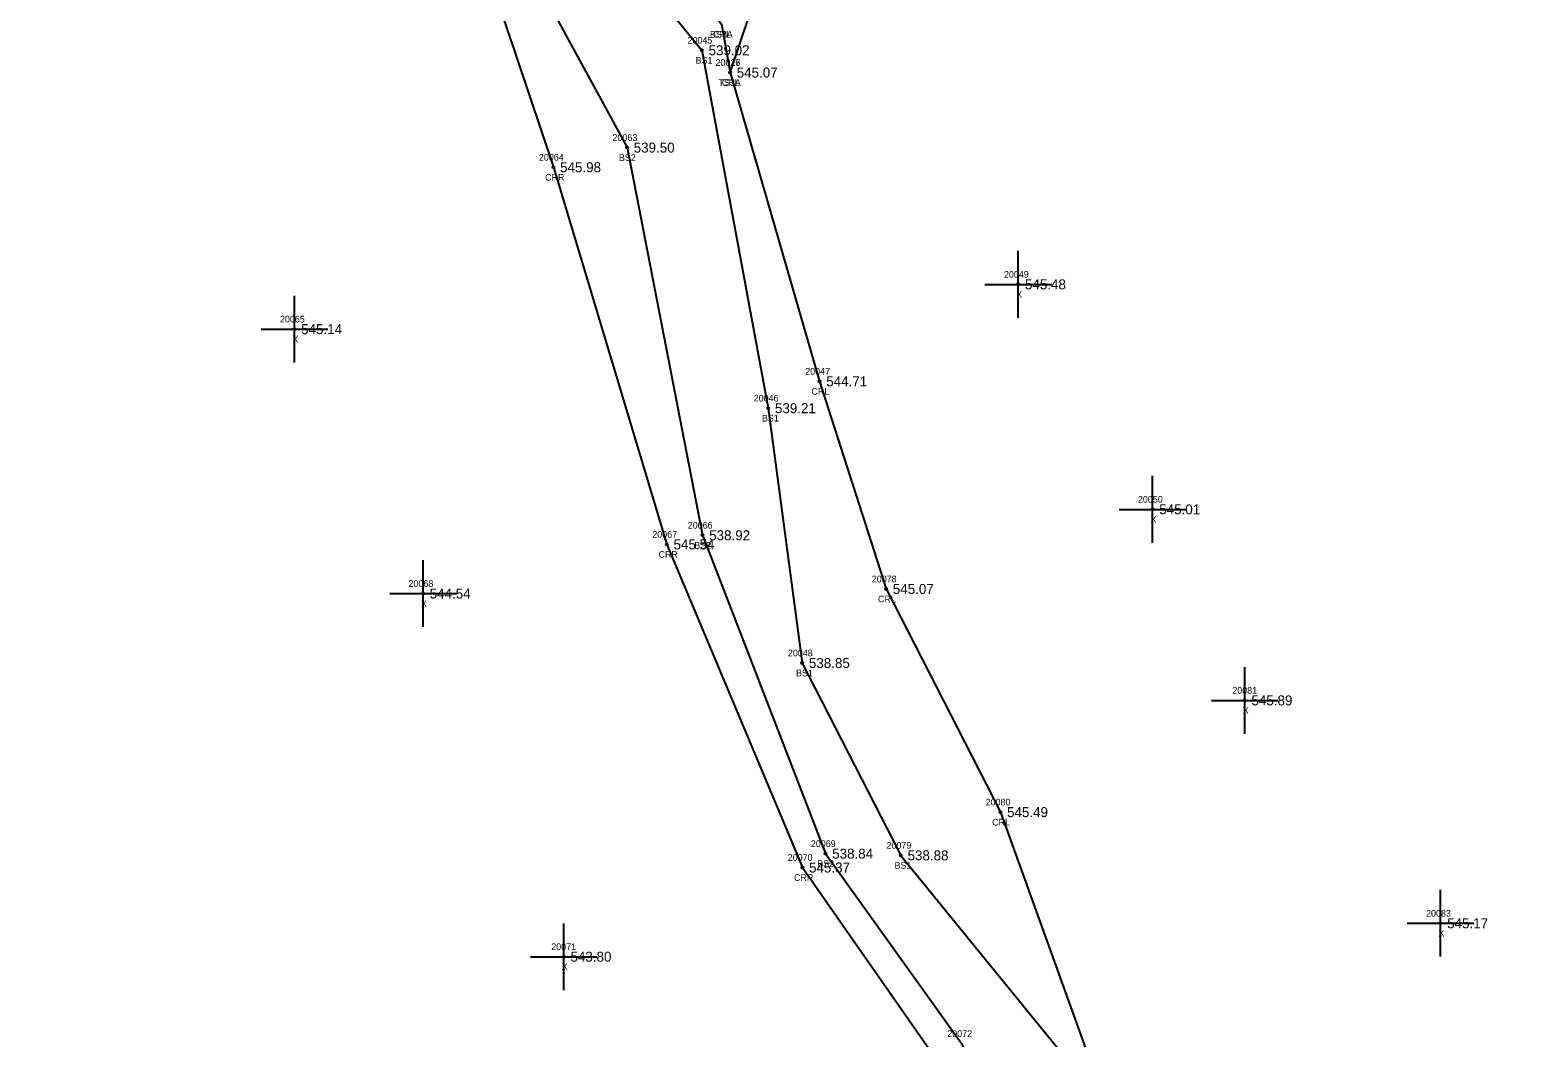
# Model space of a CAD drawing. Extents: x 1540443 to 1541844, y 887157 to 888162.
# Drawn here: x 1541137.7 to 1541363.6, y 887345.9 to 887496.8 of the extents above; entities that cross this region are included whole.
import ezdxf

# ---------------------------------------------------------------- set-up
doc = ezdxf.new("R2010")
doc.units = 0
for name, color, linetype in [('RD_DTM_BkLn2', 7, 'Continuous'), ('RD_DTM_BkLn_txCode', 7, 'Continuous'), ('RD_EX_H2O', 7, 'Continuous'), ('RD_EX_H2O_txCode', 7, 'Continuous'), ('RD_EX_Misc', 7, 'Continuous'), ('RD_EX_Misc_txCode', 7, 'Continuous'), ('RD_EX_TX_H2O_ELEV', 7, 'Continuous'), ('RD_EX_TX_Misc_ELEV', 7, 'Continuous'), ('RD_SMD_Locator', 7, 'Continuous')]:
    doc.layers.add(name, color=color, linetype=linetype)

msp = doc.modelspace()

# ---------------------------------------------------------------- linework, layer by layer
at = {"layer": 'RD_DTM_BkLn2'}
for points in [[(1541242.57, 887490.48), (1541259.05, 887539.45), (1541277.9, 887584.24), (1541281.02, 887616), (1541276.17, 887674.17)], [(1541154.57, 887667.56), (1541160.17, 887655.15), (1541167.27, 887653.55), (1541180.97, 887604.84), (1541187.58, 887570.43), (1541210.64, 887527.72), (1541238.36, 887493.82), (1541248.3, 887440.2), (1541253.39, 887402.02), (1541268.17, 887373.2), (1541292.51, 887343.28), (1541305.73, 887316.29), (1541321.44, 887255.3), (1541336.42, 887224.95), (1541338.83, 887215.6), (1541353.71, 887177.71)], [(1541146.1, 887665.49), (1541150.74, 887637.01), (1541158.36, 887596.65), (1541173.42, 887559.93), (1541207.19, 887515.92), (1541227.14, 887479.24), (1541238.45, 887421.16), (1541256.87, 887373.46), (1541277.28, 887344.99), (1541292.28, 887299.84), (1541309.01, 887259.64), (1541319.98, 887221.42), (1541339.02, 887172.82)]]:
    msp.add_lwpolyline(points, dxfattribs=at)
at = {"layer": 'RD_EX_H2O'}
for points in [[(1541162.66, 887669.25), (1541171.26, 887657.22), (1541176.19, 887641.21), (1541191.34, 887607.73), (1541196.49, 887563.9), (1541212.86, 887537.67), (1541231.05, 887519.4), (1541238.36, 887501.63), (1541241.27, 887497.71), (1541242.57, 887490.48), (1541255.99, 887444.22), (1541265.96, 887413.11), (1541283.07, 887379.68), (1541296.54, 887342.39), (1541310.03, 887318.77), (1541323.77, 887293.5), (1541326.83, 887277.23), (1541347.14, 887231.32), (1541343.88, 887214.13), (1541363.6, 887175.65)], [(1541139.32, 887662.55), (1541137.72, 887649.7), (1541145.14, 887602.62), (1541162.15, 887562.57), (1541203.5, 887513.91), (1541216.11, 887476.29), (1541233.11, 887419.79), (1541253.41, 887371.38), (1541273.08, 887343.25), (1541287.88, 887296.49), (1541302.23, 887257.73), (1541317.42, 887219.54), (1541335.4, 887172.24)]]:
    msp.add_lwpolyline(points, dxfattribs=at)
at = {"layer": 'RD_EX_Misc'}
for p, q in [((1541285.76, 887453.75), (1541285.76, 887463.75)), ((1541177.32, 887447.04), (1541177.32, 887457.04)), ((1541280.76, 887458.75), (1541290.76, 887458.75)), ((1541172.32, 887452.04), (1541182.32, 887452.04)), ((1541305.88, 887420.04), (1541305.88, 887430.04)), ((1541300.88, 887425.04), (1541310.88, 887425.04)), ((1541196.58, 887407.43), (1541196.58, 887417.43)), ((1541191.58, 887412.43), (1541201.58, 887412.43)), ((1541319.69, 887391.42), (1541319.69, 887401.42)), ((1541314.69, 887396.42), (1541324.69, 887396.42)), ((1541349.01, 887358.03), (1541349.01, 887368.03)), ((1541217.67, 887353.02), (1541217.67, 887363.02)), ((1541344.01, 887363.03), (1541354.01, 887363.03)), ((1541212.67, 887358.02), (1541222.67, 887358.02))]:
    msp.add_line(p, q, dxfattribs=at)
at = {"layer": 'RD_SMD_Locator'}
for centre in [(1541238.36, 887493.82), (1541242.57, 887490.48), (1541242.57, 887490.48), (1541227.14, 887479.24), (1541216.11, 887476.29), (1541285.76, 887458.75), (1541177.32, 887452.04), (1541255.99, 887444.22), (1541248.3, 887440.2), (1541305.88, 887425.04), (1541238.45, 887421.16), (1541233.11, 887419.79), (1541196.58, 887412.43), (1541265.96, 887413.11), (1541253.39, 887402.02), (1541319.69, 887396.42), (1541283.07, 887379.68), (1541256.87, 887373.46), (1541268.17, 887373.2), (1541253.41, 887371.38), (1541349.01, 887363.03), (1541217.67, 887358.02)]:
    msp.add_circle(centre, 0.15, dxfattribs=at)

# ---------------------------------------------------------------- texts
at = {"layer": 'RD_DTM_BkLn_txCode'}
for s, p in [('20045', (1541236.2, 887494.82)), ('BS3A', (1541239.55, 887495.71)), ('BS1', (1541237.42, 887491.82)), ('20026', (1541240.39, 887491.48)), ('TS3A', (1541240.84, 887488.48)), ('20063', (1541224.96, 887480.24)), ('BS2', (1541225.92, 887477.24)), ('20046', (1541246.12, 887441.2)), ('BS1', (1541247.35, 887438.2)), ('20066', (1541236.24, 887422.16)), ('BS2', (1541237.22, 887419.16)), ('20048', (1541251.24, 887403.02)), ('BS1', (1541252.45, 887400.02)), ('20069', (1541254.68, 887374.46)), ('20079', (1541266.01, 887374.2)), ('BS2', (1541255.64, 887371.46)), ('BS1', (1541267.22, 887371.2)), ('20072', (1541275.12, 887345.99))]:
    msp.add_text(s, height=1, dxfattribs=at).set_placement(p)
at = {"layer": 'RD_EX_H2O_txCode'}
for s, p in [('CRL', (1541240.04, 887495.71)), ('20027', (1541240.41, 887491.48)), ('CRL', (1541241.34, 887488.48)), ('20064', (1541213.93, 887477.29)), ('CRR', (1541214.86, 887474.29)), ('20047', (1541253.83, 887445.22)), ('CRL', (1541254.76, 887442.22)), ('20067', (1541230.93, 887420.79)), ('CRR', (1541231.86, 887417.79)), ('20078', (1541263.81, 887414.11)), ('CRL', (1541264.74, 887411.11)), ('20080', (1541280.87, 887380.68)), ('CRL', (1541281.84, 887377.68)), ('20070', (1541251.22, 887372.38)), ('CRR', (1541252.16, 887369.38))]:
    msp.add_text(s, height=1, dxfattribs=at).set_placement(p)
at = {"layer": 'RD_EX_Misc_txCode'}
for s, p in [('20049', (1541283.61, 887459.75)), ('X', (1541285.45, 887456.75)), ('20065', (1541175.14, 887453.04)), ('X', (1541177.01, 887450.04)), ('20050', (1541303.68, 887426.04)), ('X', (1541305.56, 887423.04)), ('20068', (1541194.4, 887413.43)), ('X', (1541196.27, 887410.43)), ('20081', (1541317.82, 887397.42)), ('X', (1541319.38, 887394.42)), ('20083', (1541346.85, 887364.03)), ('X', (1541348.7, 887361.03)), ('20071', (1541215.79, 887359.02)), ('X', (1541217.35, 887356.02))]:
    msp.add_text(s, height=1, dxfattribs=at).set_placement(p)
at = {"layer": 'RD_EX_TX_H2O_ELEV'}
for s, p in [('545.07', (1541243.57, 887489.73)), ('545.98', (1541217.11, 887475.54)), ('544.71', (1541256.99, 887443.47)), ('545.54', (1541234.11, 887419.04)), ('545.07', (1541266.96, 887412.36)), ('545.49', (1541284.07, 887378.93)), ('545.37', (1541254.41, 887370.63))]:
    msp.add_text(s, height=1.5, dxfattribs=at).set_placement(p)
at = {"layer": 'RD_EX_TX_Misc_ELEV'}
for s, p in [('539.02', (1541239.36, 887493.07)), ('545.07', (1541243.57, 887489.73)), ('539.50', (1541228.14, 887478.49)), ('545.48', (1541286.76, 887458)), ('545.14', (1541178.32, 887451.29)), ('539.21', (1541249.3, 887439.45)), ('545.01', (1541306.88, 887424.29)), ('538.92', (1541239.45, 887420.41)), ('544.54', (1541197.58, 887411.68)), ('538.85', (1541254.39, 887401.27)), ('545.89', (1541320.69, 887395.67)), ('538.84', (1541257.87, 887372.71)), ('538.88', (1541269.17, 887372.45)), ('545.17', (1541350.01, 887362.28)), ('543.80', (1541218.67, 887357.27))]:
    msp.add_text(s, height=1.5, dxfattribs=at).set_placement(p)

doc.saveas('drawing.dxf')
